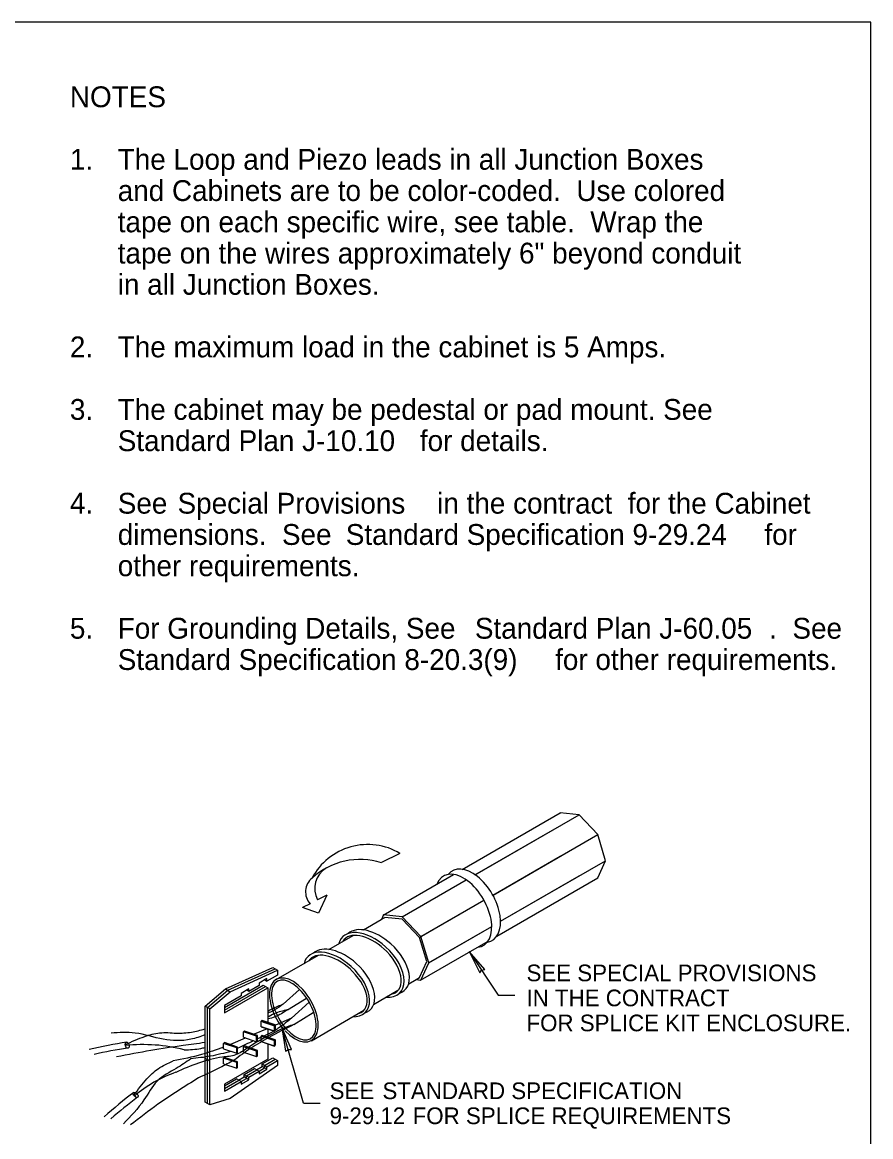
# Model space of a CAD drawing. Extents: x 99862 to 103151, y 100000 to 108076.
# Drawn here: x 102337 to 103151, y 107006 to 108076 of the extents above; entities that cross this region are included whole.
import ezdxf

# ---------------------------------------------------------------- set-up
doc = ezdxf.new("R2010")
doc.units = 0
for name, color, linetype in [('Level 1', 7, 'Continuous'), ('Level 15', 7, 'Continuous'), ('Level 2', 7, 'Continuous'), ('Level 20', 7, 'Continuous'), ('Level 21', 7, 'Continuous'), ('Level 60', 7, 'Continuous')]:
    doc.layers.add(name, color=color, linetype=linetype)

msp = doc.modelspace()

# ---------------------------------------------------------------- linework, layer by layer
at = {"layer": 'Level 1'}
msp.add_lwpolyline([(99862, 105999.5), (103151, 105999.5), (103151, 108075.5), (99862, 108075.5)], close=True, dxfattribs=at)
msp.add_lwpolyline([(99862, 105999.5), (103151, 105999.5), (103151, 108075.5), (99862, 108075.5)], close=True, dxfattribs=at)
at = {"layer": 'Level 15'}
for p, q in [((102765.8, 107184), (102793.5, 107141.9)), ((102793.5, 107141.9), (102809.5, 107141.9)), ((102606.7, 107038.2), (102586.1, 107110.9)), ((102606.7, 107038.2), (102622.7, 107038.2))]:
    msp.add_line(p, q, dxfattribs=at)
for points in [[(102765.8, 107184), (102775.8, 107163.3), (102777.7, 107165.9), (102780.8, 107166.6)], [(102586.1, 107110.9), (102589.5, 107088.1), (102592, 107089.9), (102595.2, 107089.7)]]:
    msp.add_lwpolyline(points, close=True, dxfattribs=at)
at = {"layer": 'Level 2'}
for p, q in [((102759.1, 107262.6), (102853.1, 107316.9)), ((102771.4, 107257.5), (102871.1, 107315.1)), ((102853.1, 107316.9), (102852.9, 107316.4)), ((102871.1, 107315.1), (102853.1, 107316.9)), ((102889.1, 107296.1), (102871.1, 107315.1)), ((102771.3, 107257.4), (102845.7, 107300.4)), ((102788.4, 107237.9), (102886.1, 107294.3)), ((102788.6, 107238), (102889.1, 107296.1)), ((102896.6, 107271), (102889.1, 107296.1)), ((102699.3, 107278), (102681.6, 107269.1)), ((102788.3, 107237.8), (102853.1, 107275.3)), ((102788.3, 107237.8), (102852.7, 107275.1)), ((102795.8, 107212.8), (102896.6, 107271)), ((102889.1, 107254.5), (102896.6, 107271)), ((102683.1, 107218.7), (102750.7, 107257.7)), ((102701.3, 107217), (102762.8, 107252.6)), ((102701.4, 107217.1), (102762.8, 107252.6)), ((102792.1, 107198.5), (102889.1, 107254.5)), ((102795.8, 107212.8), (102871.1, 107256.3)), ((102629.2, 107237.8), (102620.3, 107233.4)), ((102613, 107229.7), (102605.7, 107226)), ((102718.1, 107197.3), (102780, 107233.1)), ((102719.1, 107197.9), (102780.1, 107233.1)), ((102719.4, 107198.1), (102779.9, 107233)), ((102719.4, 107198.1), (102779.9, 107233)), ((102681.4, 107214.7), (102684.9, 107216.6)), ((102683.4, 107218.9), (102681.5, 107214.7)), ((102701.4, 107217.1), (102683.4, 107218.9)), ((102701.4, 107215), (102684.7, 107216.6)), ((102719.4, 107198.1), (102701.4, 107217.1)), ((102664.2, 107204.8), (102681.4, 107214.7)), ((102718.1, 107197.3), (102701.4, 107215)), ((102726.7, 107172.9), (102787.4, 107208)), ((102726.9, 107173), (102787.4, 107208)), ((102630.9, 107185.8), (102654.4, 107199.3)), ((102725, 107174.1), (102718.1, 107197.3)), ((102726.9, 107173), (102719.4, 107198.1)), ((102719, 107156.3), (102783.9, 107193.8)), ((102580.5, 107157), (102621.1, 107180.2)), ((102718.1, 107158.8), (102725, 107174.1)), ((102719.4, 107156.5), (102726.9, 107173)), ((102577.3, 107168.6), (102581.8, 107166)), ((102581.8, 107166), (102581.8, 107161.3)), ((102564.2, 107151.2), (102554.4, 107145.5)), ((102571.7, 107158), (102564.2, 107153.6)), ((102564.2, 107153.6), (102564.2, 107151.2)), ((102568, 107151.6), (102572.5, 107149)), ((102569.5, 107156.7), (102571.7, 107155.5)), ((102581.8, 107161.3), (102571.7, 107155.5)), ((102571.7, 107155.5), (102571.7, 107158)), ((102707.9, 107152.8), (102715, 107157)), ((102715, 107157), (102718.1, 107158.8)), ((102715, 107157), (102715, 107157)), ((102715, 107157), (102719.4, 107156.5)), ((102530.9, 107125), (102572.5, 107149)), ((102531.8, 107147.9), (102536.3, 107145.3)), ((102554.4, 107148), (102546.9, 107143.7)), ((102546.9, 107143.7), (102546.9, 107141.2)), ((102554.4, 107145.5), (102552.3, 107146.8)), ((102554.4, 107145.5), (102554.4, 107148)), ((102572.5, 107149), (102572.5, 107116)), ((102673.9, 107132.9), (102697.2, 107146.6)), ((102516.8, 107128.8), (102512.3, 107131.4)), ((102614.3, 107098.1), (102664.6, 107127.5)), ((102567, 107117.7), (102566.2, 107116.9)), ((102566.2, 107111.7), (102566.2, 107116.9)), ((102567, 107116.6), (102566.2, 107116.9)), ((102566.2, 107111.7), (102578.8, 107107.4)), ((102578.8, 107107.4), (102566.5, 107111.6)), ((102579.6, 107113.4), (102567, 107117.7)), ((102578.8, 107112.6), (102567, 107116.6)), ((102567.3, 107117.6), (102579.6, 107113.4)), ((102567.3, 107116.5), (102578.8, 107112.6)), ((102579.6, 107113.4), (102578.8, 107112.6)), ((102579.6, 107113.4), (102578.8, 107112.6)), ((102578.8, 107112.6), (102578.8, 107107.4)), ((102578.8, 107107.4), (102578.8, 107112.6)), ((102579.6, 107113.4), (102579.6, 107108.2)), ((102579.6, 107108.2), (102579.6, 107113.4)), ((102550, 107107.5), (102549.2, 107106.7)), ((102549.2, 107101.5), (102549.2, 107106.7)), ((102550, 107106.4), (102549.2, 107106.7)), ((102549.2, 107101.5), (102561.8, 107097.3)), ((102562.6, 107103.3), (102550, 107107.5)), ((102561.8, 107102.5), (102550, 107106.4)), ((102562.6, 107103.3), (102561.8, 107102.5)), ((102561.8, 107097.3), (102561.8, 107102.5)), ((102561.8, 107097.3), (102562.6, 107098.1)), ((102562.6, 107098.1), (102562.6, 107103.3)), ((102567, 107103.4), (102566.2, 107102.6)), ((102566.2, 107097.4), (102566.2, 107102.6)), ((102567, 107102.3), (102566.2, 107102.6)), ((102579.6, 107099.2), (102567, 107103.4)), ((102578.8, 107098.4), (102567, 107102.3)), ((102567.3, 107103.3), (102579.6, 107099.2)), ((102567.3, 107102.2), (102578.8, 107098.4)), ((102578.8, 107107.4), (102579.6, 107108.2)), ((102578.8, 107107.4), (102579.6, 107108.2)), ((102579.6, 107099.2), (102578.8, 107098.4)), ((102579.6, 107099.2), (102578.8, 107098.4)), ((102578.8, 107098.4), (102578.8, 107093.1)), ((102578.8, 107093.1), (102578.8, 107098.4)), ((102579.6, 107099.2), (102579.6, 107093.9)), ((102579.6, 107093.9), (102579.6, 107099.2)), ((102530.9, 107096.5), (102530.1, 107095.7)), ((102530.1, 107090.5), (102530.1, 107095.7)), ((102530.9, 107095.4), (102530.1, 107095.7)), ((102530.1, 107090.5), (102542.7, 107086.2)), ((102530.1, 107090.5), (102542.7, 107086.2)), ((102543.5, 107092.2), (102530.9, 107096.5)), ((102543.5, 107092.2), (102530.9, 107096.5)), ((102542.7, 107091.4), (102530.9, 107095.4)), ((102542.7, 107091.4), (102530.9, 107095.4)), ((102543.5, 107092.2), (102542.7, 107091.4)), ((102543.5, 107092.2), (102542.7, 107091.4)), ((102542.7, 107086.2), (102542.7, 107091.4)), ((102542.7, 107086.2), (102542.7, 107091.4)), ((102542.7, 107086.2), (102543.5, 107087)), ((102542.7, 107086.2), (102543.5, 107087)), ((102543.5, 107087), (102543.5, 107092.2)), ((102543.5, 107087), (102543.5, 107092.2)), ((102550, 107093.2), (102549.2, 107092.4)), ((102549.2, 107087.2), (102549.2, 107092.4)), ((102550, 107092.2), (102549.2, 107092.4)), ((102549.2, 107087.2), (102561.8, 107083)), ((102549.2, 107087.2), (102561.8, 107083)), ((102562.6, 107089), (102550, 107093.2)), ((102562.6, 107089), (102550, 107093.2)), ((102561.8, 107088.2), (102550, 107092.2)), ((102561.8, 107088.2), (102550, 107092.2)), ((102562.6, 107089), (102561.8, 107088.2)), ((102562.6, 107089), (102561.8, 107088.2)), ((102561.8, 107083), (102561.8, 107088.2)), ((102561.8, 107083), (102561.8, 107088.2)), ((102562.6, 107083.8), (102562.6, 107089)), ((102562.6, 107083.8), (102562.6, 107089)), ((102566.2, 107097.4), (102578.8, 107093.1)), ((102578.8, 107093.1), (102566.5, 107097.3)), ((102572.5, 107095.3), (102572.5, 107080.4)), ((102578.8, 107093.1), (102579.6, 107093.9)), ((102578.8, 107093.1), (102579.6, 107093.9)), ((102516.8, 107078.7), (102512.3, 107081.3)), ((102516.8, 107036.6), (102516.8, 107078.7)), ((102530.9, 107082.2), (102530.1, 107081.4)), ((102530.1, 107076.2), (102530.1, 107081.4)), ((102530.9, 107081.1), (102530.1, 107081.4)), ((102543.5, 107077.9), (102530.9, 107082.2)), ((102543.5, 107077.9), (102530.9, 107082.2)), ((102542.7, 107077.2), (102530.9, 107081.1)), ((102542.7, 107077.2), (102530.9, 107081.1)), ((102572.5, 107080.4), (102530.9, 107056.4)), ((102543.5, 107077.9), (102542.7, 107077.2)), ((102543.5, 107077.9), (102542.7, 107077.2)), ((102542.7, 107071.9), (102542.7, 107077.2)), ((102542.7, 107071.9), (102542.7, 107077.2)), ((102543.5, 107072.7), (102543.5, 107077.9)), ((102543.5, 107072.7), (102543.5, 107077.9)), ((102561.8, 107083), (102562.6, 107083.8)), ((102561.8, 107083), (102562.6, 107083.8)), ((102567.2, 107075.9), (102577.3, 107081.8)), ((102569.4, 107074.6), (102579.6, 107080.4)), ((102571.7, 107073.3), (102581.8, 107079.1)), ((102577.3, 107081.8), (102581.8, 107079.1)), ((102581.8, 107079.1), (102581.8, 107074.5)), ((102530.1, 107076.2), (102542.7, 107071.9)), ((102530.1, 107076.2), (102542.7, 107071.9)), ((102581.8, 107074.5), (102536.3, 107042.7)), ((102542.7, 107071.9), (102543.5, 107072.7)), ((102542.7, 107071.9), (102543.5, 107072.7)), ((102549.9, 107065.9), (102559.7, 107071.6)), ((102549.9, 107063.5), (102549.9, 107065.9)), ((102549.9, 107065.9), (102554.4, 107063.3)), ((102552.2, 107064.6), (102561.9, 107070.3)), ((102554.4, 107063.3), (102564.2, 107069)), ((102559.7, 107071.6), (102564.2, 107069)), ((102561.8, 107070.3), (102567.2, 107073.4)), ((102564.1, 107069), (102569.4, 107072.1)), ((102564.2, 107066.5), (102571.7, 107070.8)), ((102564.2, 107069), (102564.2, 107066.5)), ((102567.2, 107073.4), (102567.2, 107075.9)), ((102567.2, 107075.9), (102571.7, 107073.3)), ((102571.7, 107070.8), (102567.2, 107073.4)), ((102569.4, 107072.1), (102569.4, 107074.6)), ((102571.7, 107070.8), (102571.7, 107073.3)), ((102546.9, 107059), (102542.4, 107061.6)), ((102544.5, 107060.4), (102549.9, 107063.5)), ((102546.8, 107059.1), (102552.2, 107062.1)), ((102546.9, 107056.5), (102554.4, 107060.8)), ((102546.9, 107059), (102546.9, 107056.5)), ((102554.4, 107060.8), (102549.9, 107063.5)), ((102552.2, 107062.1), (102552.2, 107064.6)), ((102554.4, 107060.8), (102554.4, 107063.3)), ((102516.8, 107036.6), (102512.3, 107039.2)), ((102536.3, 107042.7), (102516.8, 107036.6))]:
    msp.add_line(p, q, dxfattribs=at)
for points in [[(102889.1, 107254.5), (102889.1, 107254.5), (102896.6, 107271), (102889.1, 107296.1), (102871.1, 107315.1), (102853.1, 107316.9)], [(102629.2, 107237.8), (102621, 107220.6), (102605.7, 107226)], [(102512.3, 107081.3), (102512.3, 107131.4), (102531.8, 107147.9), (102577.3, 107168.6)], [(102514.6, 107080), (102514.6, 107130.1), (102534.1, 107146.6), (102579.6, 107167.3)], [(102516.8, 107078.7), (102516.8, 107128.8), (102536.3, 107145.3), (102581.8, 107166)], [(102530.9, 107130.2), (102568, 107151.6)], [(102530.9, 107127.6), (102570.2, 107150.3)], [(102546.9, 107141.2), (102530.9, 107131.9), (102530.9, 107125)], [(102572.5, 107109.7), (102572.5, 107101.6)], [(102512.3, 107039.2), (102512.3, 107081.3)], [(102514.6, 107037.9), (102514.6, 107080)], [(102530.9, 107054.9), (102542.4, 107061.6)], [(102530.9, 107052.3), (102544.7, 107060.3)], [(102530.9, 107056.4), (102530.9, 107049.7), (102546.9, 107059)]]:
    msp.add_lwpolyline(points, dxfattribs=at)
for centre, radius, start, end in [((102668.4, 107226), 60.5, 59.2611, 152.03), ((102661.1, 107203.8), 68.4, 72.5854, 132.3908), ((102640.4, 107244.4), 22.9, 120.6886, 208.815), ((102625.7, 107241.1), 17, 128.8772, 222.0079)]:
    msp.add_arc(centre, radius, start, end, dxfattribs=at)
for centre, major_axis, ratio, start_param, end_param in [((102760.2, 107222.9), (19.2, -33.3), 0.57735, 6.020187, 9.853771), ((102768.7, 107227.8), (19.2, -33.3), 0.57735, 6.060375, 9.654715), ((102676.7, 107173.8), (27.7, -26.6), 0.57735, 1.623748, 3.103985), ((102671.7, 107171), (27.7, -26.6), 0.57735, 1.623748, 3.452595), ((102671.8, 107170.6), (26, -24.9), 0.549174, 1.623748, 3.249842), ((102638.5, 107152.2), (27.7, -26.6), 0.57735, 1.623748, 3.472013), ((102643.5, 107155), (27.7, -26.6), 0.57735, 1.623748, 3.103985), ((102671.2, 107171.2), (26, -24.9), 0.549174, 6.001457, 7.906933), ((102671.7, 107171), (27.7, -26.6), 0.57735, 5.685388, 7.906933), ((102676.7, 107173.8), (27.7, -26.6), 0.57735, 5.983608, 7.906933), ((102639.1, 107151.6), (26, -24.9), 0.549174, 1.623748, 3.249842), ((102597.5, 107127.7), (16.9, -29.3), 0.551009, 5.106511, 11.365489), ((102638.5, 107152.2), (26, -24.9), 0.549174, 6.001457, 7.906933), ((102638.5, 107152.2), (27.7, -26.6), 0.57735, 5.715215, 7.906933), ((102643.5, 107155), (27.7, -26.6), 0.57735, 5.967322, 7.906933), ((102597.5, 107127.7), (15.9, -27.5), 0.521167, 5.101279, 11.368406)]:
    msp.add_ellipse(centre, major_axis=major_axis, ratio=ratio, start_param=start_param, end_param=end_param, dxfattribs=at)
at = {"layer": 'Level 21'}
for p, q in [((102587.3, 107133.3), (102602.9, 107147.3)), ((102591.3, 107127.9), (102609.5, 107139.2)), ((102595.2, 107119.9), (102612.1, 107135.1)), ((102595.2, 107119.9), (102579.8, 107113.1)), ((102597.5, 107113.9), (102616.1, 107125.4)), ((102572, 107109.8), (102559.4, 107104.4)), ((102550.9, 107100.8), (102536.7, 107094.7))]:
    msp.add_line(p, q, dxfattribs=at)
for centre, radius, start, end in [((102518.9, 106570.5), 532.6, 98.8042, 102.7736), ((102518.9, 106570.5), 526.9, 98.8042, 102.3942), ((102453.3, 106939), 155.5, 75.503, 96.3909), ((102526.2, 106948.7), 126.4, 109.4222, 130.3101), ((102766.4, 106624.7), 532.6, 127.2471, 131.2166), ((102766.4, 106624.7), 526.9, 127.2471, 130.8372)]:
    msp.add_arc(centre, radius, start, end, dxfattribs=at)
for centre, major_axis in [((102437.6, 107093.9), (-0.82, 2.91)), ((102445.7, 107046.2), (-2.1, 2.17))]:
    msp.add_ellipse(centre, major_axis=major_axis, ratio=0.557118, dxfattribs=at)
for points in [[(102587.3, 107133.3), (102576.4, 107128.5), (102572.7, 107126.5)], [(102587.3, 107133.3), (102579.2, 107127.8), (102577.3, 107126.7), (102572.8, 107124.8)], [(102595.2, 107119.9), (102583.1, 107110.5), (102579.6, 107108.2), (102562.7, 107100.1)], [(102591.3, 107127.9), (102578.7, 107124.1), (102572.3, 107120.7)], [(102591.3, 107127.9), (102579.4, 107121.1), (102572.7, 107119.1)], [(102597.5, 107113.9), (102584.7, 107108.9), (102575.1, 107104), (102564.7, 107098.5), (102552.8, 107091.1), (102541.5, 107084.6), (102529, 107082.5), (102484.2, 107067.9)], [(102484.8, 107105.4), (102499.2, 107106.5), (102512, 107109.6)], [(102597.5, 107113.9), (102573.5, 107101.2), (102556.3, 107091.1), (102540.1, 107079.5)], [(102512.2, 107103.8), (102498.6, 107099.6), (102472.2, 107099.6), (102445.2, 107105.6), (102422.1, 107105.6)], [(102436, 107094.6), (102454.4, 107102.3), (102468.7, 107105.8), (102484.8, 107105.4)], [(102558.8, 107098.3), (102558.6, 107098.2), (102543.6, 107091)], [(102512, 107096.4), (102491.2, 107093.6), (102460.4, 107088.8), (102427.3, 107082.7)], [(102530, 107092), (102508.9, 107085), (102481.7, 107078.8)], [(102492.2, 107089.5), (102508.3, 107090.9), (102512, 107091.8)], [(102537.2, 107088), (102517.5, 107083.4), (102498.6, 107080.9)], [(102498.6, 107080.9), (102484.7, 107071.7), (102466.4, 107059.4), (102453.7, 107041.4), (102434, 107018.5)], [(102444, 107046), (102456.5, 107061.6), (102467.3, 107071.4), (102481.7, 107078.8)], [(102540.1, 107079.5), (102526.7, 107072.4), (102506, 107062.6)], [(102506, 107062.6), (102467.1, 107037.2), (102440.7, 107017.4)]]:
    msp.add_spline(points, degree=3, dxfattribs=at)
at = {"layer": 'Level 60'}
msp.add_line((103151, 108075.5), (103151, 108075.5), dxfattribs=at)
msp.add_line((103151, 108075.5), (103151, 108075.5), dxfattribs=at)
msp.add_line((103151, 108075.5), (103151, 108075.5), dxfattribs=at)
msp.add_line((103151, 108075.5), (103151, 108075.5), dxfattribs=at)

# ---------------------------------------------------------------- texts
at = {"layer": 'Level 20'}
for s, height, p in [('NOTES', 20, (102382.6, 107994)), ('1.', 20, (102382.6, 107934)), ('The Loop and Piezo leads in all Junction Boxes ', 20, (102428.5, 107934)), ('and Cabinets are to be color-coded.  Use colored ', 20, (102428.5, 107904)), ('tape on each specific wire, see table.  Wrap the ', 20, (102428.5, 107874)), ('tape on the wires approximately 6" beyond conduit ', 20, (102428.5, 107844)), ('in all Junction Boxes.', 20, (102428.5, 107814)), ('2.', 20, (102382.6, 107754)), ('The maximum load in the cabinet is 5 Amps.', 20, (102428.5, 107754)), ('3.', 20, (102382.6, 107694)), ('The cabinet may be pedestal or pad mount. See ', 20, (102428.5, 107694)), ('Standard Plan J-10.10 ', 20, (102428.5, 107664)), ('for details.                                     ', 20, (102718.4, 107664)), ('4.', 20, (102382.6, 107604)), ('See ', 20, (102428.5, 107604)), ('Special Provisions ', 20, (102485.9, 107604)), ('in the contract  for the Cabinet ', 20, (102735, 107604)), ('dimensions.  See', 20, (102428.5, 107574)), (' Standard Specification 9-29.24 ', 20, (102639.9, 107574)), ('for ', 20, (103049, 107574)), ('other requirements. ', 20, (102428.5, 107544)), ('For Grounding Details, See ', 20, (102428.5, 107484)), ('Standard Plan J-60.05', 20, (102771.2, 107484)), ('.  See ', 20, (103053.6, 107484)), ('5.', 20, (102382.6, 107484)), ('Standard Specification 8-20.3(9) ', 20, (102428.5, 107454)), ('for other requirements. ', 20, (102848.2, 107454)), ('SEE SPECIAL PROVISIONS ', 16, (102820.7, 107155.3)), ('IN THE CONTRACT', 16, (102820.7, 107131.3)), ('FOR SPLICE KIT ENCLOSURE.', 16, (102820.7, 107107.3)), ('SEE ', 16, (102631.8, 107042.2)), ('STANDARD SPECIFICATION ', 16, (102682.5, 107042.2)), ('9-29.12 ', 16, (102631.8, 107018.2)), ('FOR SPLICE REQUIREMENTS', 16, (102711.5, 107018.2))]:
    msp.add_text(s, height=height, dxfattribs=at).set_placement(p)

doc.saveas('drawing.dxf')
